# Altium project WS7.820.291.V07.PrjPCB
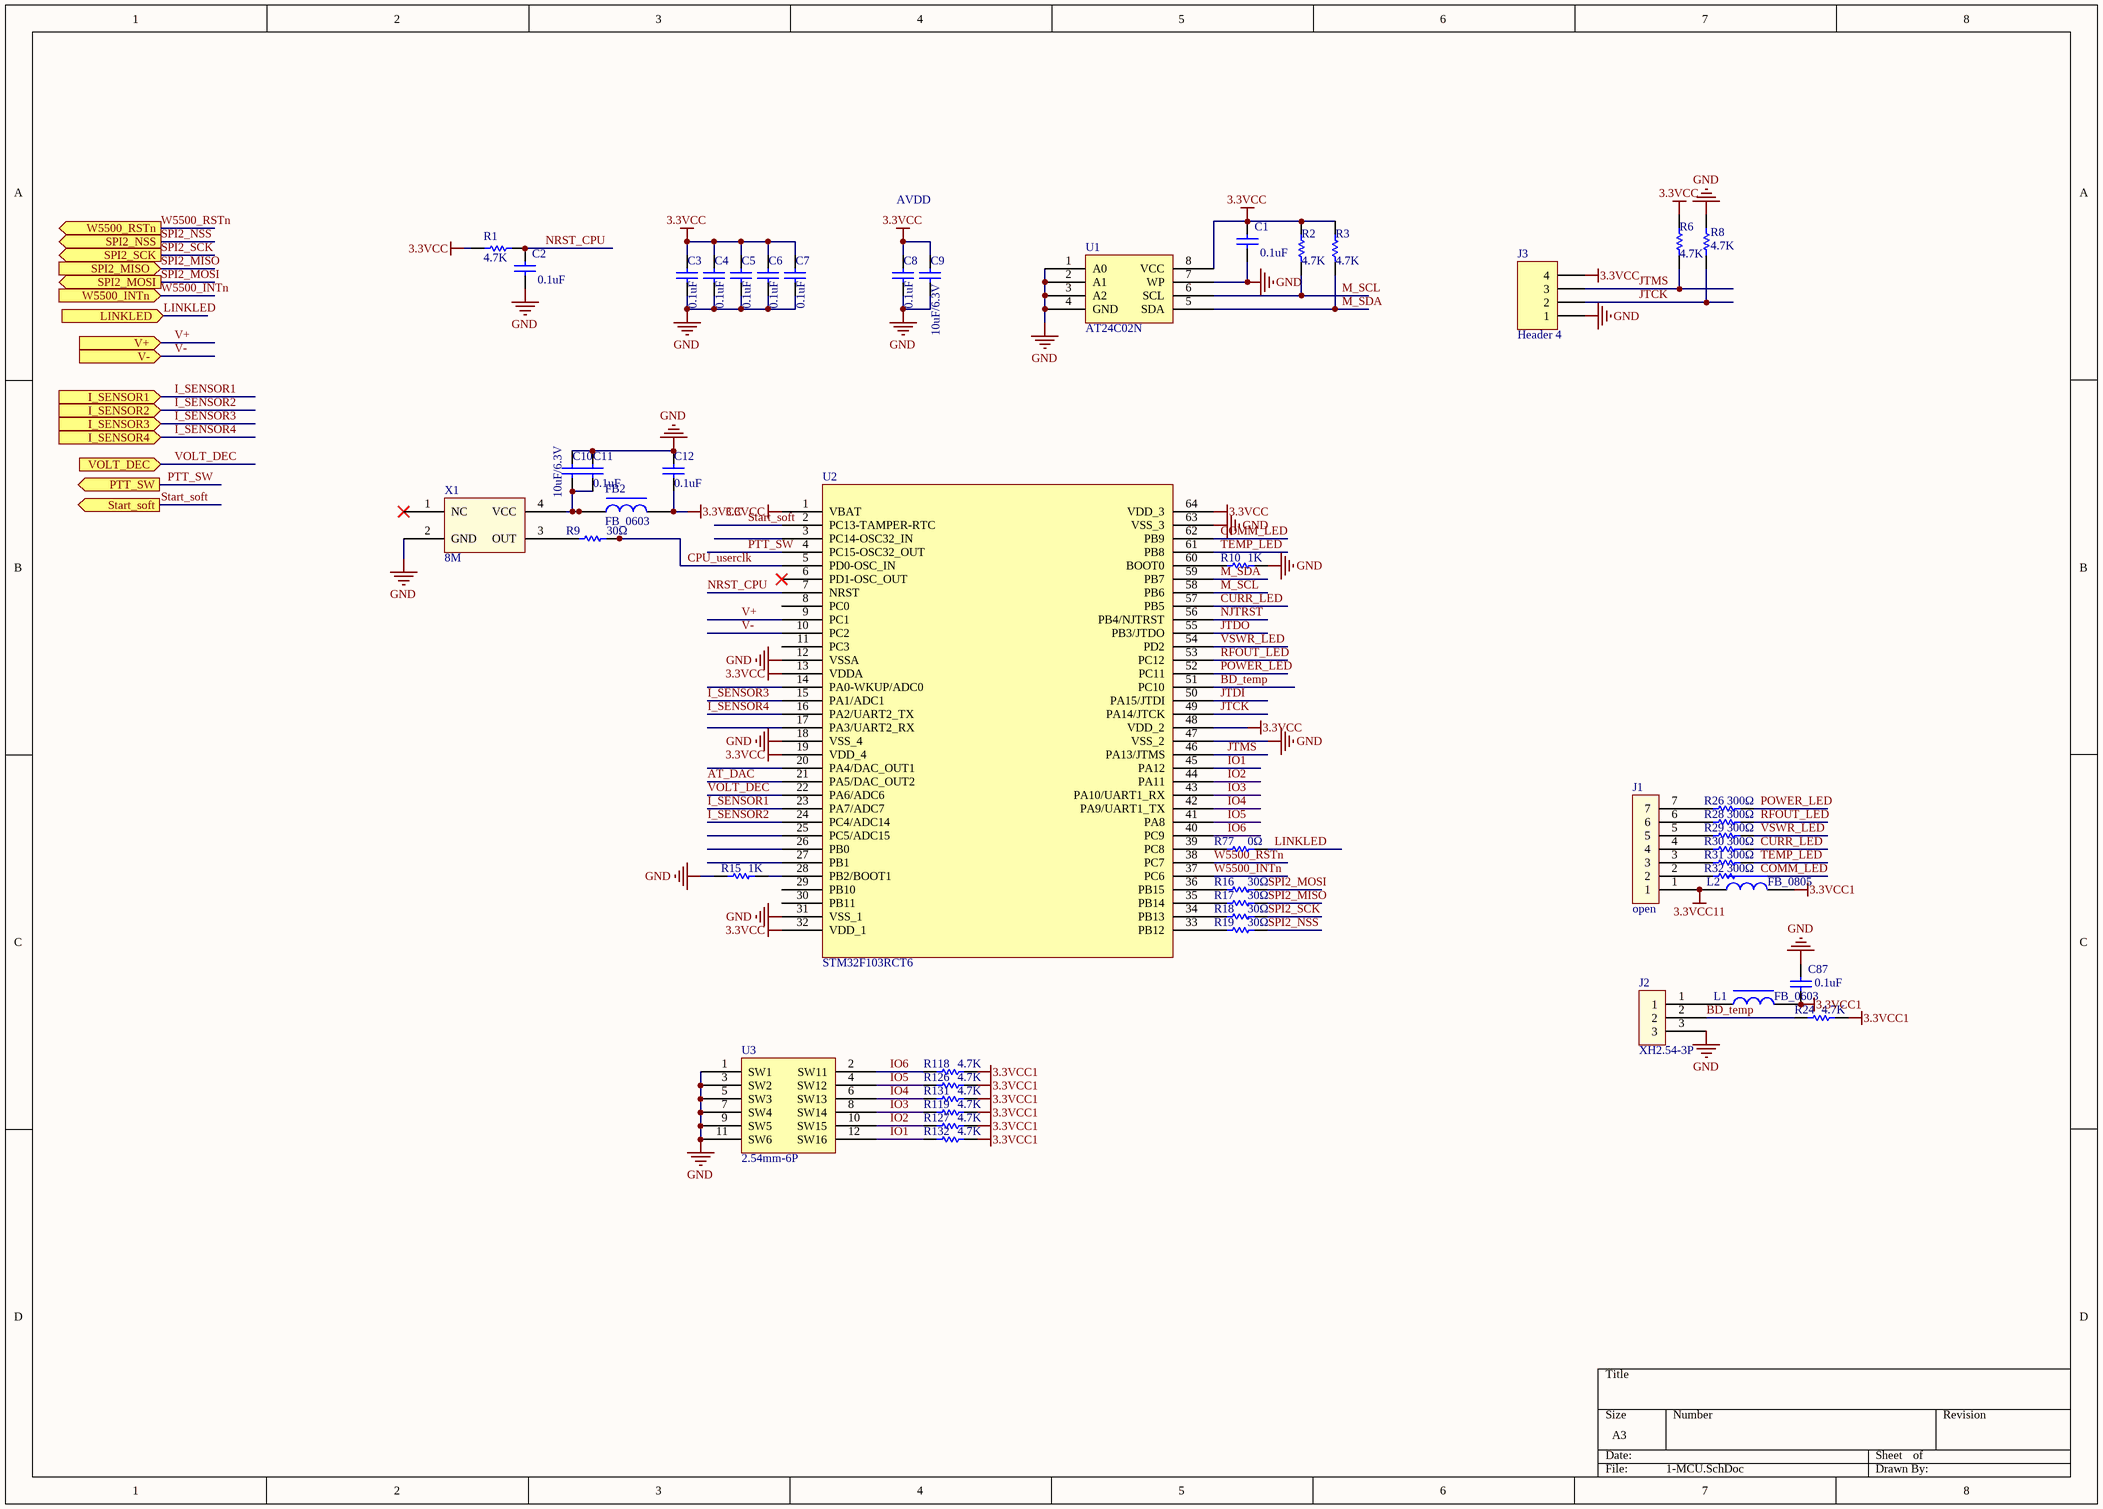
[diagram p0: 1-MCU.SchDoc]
4 sheets, 262 parts. Net scope: flat (ports and power ports of the same name join across sheets).
Board file: WS7.820.291.V07.PcbDoc
Sheets:
  1-MCU.SchDoc
  2-RJ45.SchDoc
  3-RF.SchDoc
  4-POWER.SchDoc

## Sheet 1-MCU.SchDoc
size A3

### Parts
C1  0.1uF  [C0603]
C2  0.1uF  [C0603]
C3  0.1uF  [C0603]
C4  0.1uF  [C0603]
C5  0.1uF  [C0603]
C6  0.1uF  [C0603]
C7  0.1uF  [C0603]
C8  0.1uF  [C0603]
C9  10uF/6.3V  [C0603]
C10  10uF/6.3V  [C0603]
C11  0.1uF  [C0603]
C12  0.1uF  [C0603]
C87  0.1uF  [C0603]
FB2  FB_0603  [L0603]
J1  open  [KF2510-7P -2R54-17R8x6R0-wanzhen]
J2  XH2.54-3P  [XH2.54mm-10R0x7R0--zhizhen]
J3  Header 4  [HDR1X4]
L1  FB_0603  [L0603]
L2  FB_0805  [L0805]
R1  4.7K  [R0603]
R2  4.7K  [R0603]
R3  4.7K  [R0603]
R6  4.7K  [R0603]
R8  4.7K  [R0603]
R9  30Ω  [R0603]
R10  1K  [R0603]
R15  1K  [R0603]
R16  30Ω  [R0603]
R17  30Ω  [R0603]
R18  30Ω  [R0603]
R19  30Ω  [R0603]
R24  4.7K  [R0603]
R26  300Ω  [R0603]
R28  300Ω  [R0603]
R29  300Ω  [R0603]
R30  300Ω  [R0603]
R31  300Ω  [R0603]
R32  300Ω  [R0603]
R77  0Ω  [R0603]
R118  4.7K  [R0603]
R119  4.7K  [R0603]
R126  4.7K  [R0603]
R127  4.7K  [R0603]
R131  4.7K  [R0603]
R132  4.7K  [R0603]
U1  AT24C02N  [SOIC8_1R27_3R9x4R9]
U2  STM32F103RCT6  [LQFP64-0R50-10x10]
U3  2.54mm-6P  [con12TM-2R54-2X6-boma]
X1  8M  [CRY4SM-5R0x7R0]

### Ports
I_SENSOR1 (in), I_SENSOR2 (in), I_SENSOR3 (in), I_SENSOR4 (in), LINKLED (in), PTT_SW (out), SPI2_MISO (in), SPI2_MOSI (out), SPI2_NSS (out), SPI2_SCK (out), Start_soft (out), V+ (in), V- (in), VOLT_DEC (in), W5500_INTn (in), W5500_RSTn (out)

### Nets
3.3VCC: C1.2 C3.2 C4.2 C5.2 C6.2 C7.2 C8.2 C9.2 C12.1 FB2.2 J3.4 R1.2 R2.2 R3.2 R6.2 U1.8(VCC) U2.1(VBAT) U2.13(VDDA) U2.19(VDD_4) U2.32(VDD_1) U2.48(VDD_2) U2.64(VDD_3)
3.3VCC1: C87.2 L1.2 L2.2 R24.1 R118.2 R119.2 R126.2 R127.2 R131.2 R132.2
3.3VCC11: J1.1 L2.1
GND: C1.1 C2.1 C3.1 C4.1 C5.1 C6.1 C7.1 C8.1 C9.1 C10.1 C11.2 C12.2 C87.1 J2.3 J3.1 R8.1 R10.1 R15.1 U1.1(A0) U1.2(A1) U1.3(A2) U1.4(GND) U1.7(WP) U2.12(VSSA) U2.18(VSS_4) U2.31(VSS_1) U2.47(VSS_2) U2.63(VSS_3) U3.1(SW1) U3.3(SW2) U3.5(SW3) U3.7(SW4) U3.9(SW5) U3.11(SW6) X1.2(GND)
AT_DAC: U2.21(PA5/DAC_OUT2)
BD_temp: J2.2 R24.2 U2.51(PC10)
COMM_LED: R32.2 U2.62(PB9)
CPU_userclk: R9.2 U2.5(PD0-OSC_IN)
CURR_LED: R30.2 U2.57(PB5)
I_SENSOR1: U2.23(PA7/ADC7) ; port I_SENSOR1
I_SENSOR2: U2.24(PC4/ADC14) ; port I_SENSOR2
I_SENSOR3: U2.15(PA1/ADC1) ; port I_SENSOR3
I_SENSOR4: U2.16(PA2/UART2_TX) ; port I_SENSOR4
IO1: R132.1 U2.45(PA12) U3.12(SW16)
IO2: R127.1 U2.44(PA11) U3.10(SW15)
IO3: R119.1 U2.43(PA10/UART1_RX) U3.8(SW14)
IO4: R131.1 U2.42(PA9/UART1_TX) U3.6(SW13)
IO5: R126.1 U2.41(PA8) U3.4(SW12)
IO6: R118.1 U2.40(PC9) U3.2(SW11)
JTCK: J3.2 R8.2 U2.49(PA14/JTCK)
JTDI: U2.50(PA15/JTDI)
JTDO: U2.55(PB3/JTDO)
JTMS: J3.3 R6.1 U2.46(PA13/JTMS)
LINKLED: R77.2 ; port LINKLED
M_SCL: R2.1 U1.6(SCL) U2.58(PB6)
M_SDA: R3.1 U1.5(SDA) U2.59(PB7)
NJTRST: U2.56(PB4/NJTRST)
NRST_CPU: C2.2 R1.1 U2.7(NRST)
POWER_LED: R26.2 U2.52(PC11)
PTT_SW: U2.4(PC15-OSC32_OUT) ; port PTT_SW
RFOUT_LED: R28.2 U2.53(PC12)
SPI2_MISO: R17.2 ; port SPI2_MISO
SPI2_MOSI: R16.2 ; port SPI2_MOSI
SPI2_NSS: R19.2 ; port SPI2_NSS
SPI2_SCK: R18.2 ; port SPI2_SCK
Start_soft: U2.2(PC13-TAMPER-RTC) ; port Start_soft
TEMP_LED: R31.2 U2.61(PB8)
V+: U2.9(PC1) ; port V+
V-: U2.10(PC2) ; port V-
VOLT_DEC: U2.22(PA6/ADC6) ; port VOLT_DEC
VSWR_LED: R29.2 U2.54(PD2)
W5500_INTn: U2.37(PC6) ; port W5500_INTn
W5500_RSTn: U2.38(PC7) ; port W5500_RSTn
NetC10_2: C10.2 C11.1 FB2.1 X1.4(VCC)
NetJ1_2: J1.2 R32.1
NetJ1_3: J1.3 R31.1
NetJ1_4: J1.4 R30.1
NetJ1_5: J1.5 R29.1
NetJ1_6: J1.6 R28.1
NetJ1_7: J1.7 R26.1
NetJ2_1: J2.1 L1.1
NetR9_1: R9.1 X1.3(OUT)
NetR10_2: R10.2 U2.60(BOOT0)
NetR15_2: R15.2 U2.28(PB2/BOOT1)
NetR16_1: R16.1 U2.36(PB15)
NetR17_1: R17.1 U2.35(PB14)
NetR18_1: R18.1 U2.34(PB13)
NetR19_1: R19.1 U2.33(PB12)
NetR77_1: R77.1 U2.39(PC8)

Not connected (* = marked no-connect by the designer): U2 3(PC14-OSC32_IN) 6(PD1-OSC_OUT)* 8(PC0) 11(PC3) 14(PA0-WKUP/ADC0) 17(PA3/UART2_RX) 20(PA4/DAC_OUT1) 25(PC5/ADC15) 26(PB0) 27(PB1) 29(PB10) 30(PB11); X1 1(NC)*

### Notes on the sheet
- AVDD

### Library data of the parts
C1-C8 C11 C12 = 0.1uF贴片电容: 贴片电容_GRM188R71H104KA01D_0.1uF±10%,50V,0603; code: 01010045
C9 C10 = 10uF贴片电容: 贴片电容_GRM188R60J106ME47D_10uF±20%,6.3V,0603; code: 01010037
C87 = 0.1uF: GRM188R71H104KA01D; MPN: MURATA; WSPN: 01010045; DESCRIPTION: CAP,0.1uF,±10%,50V,X7R,0603
FB2 = 0603贴片磁珠: 贴片磁珠_100R,0603; code: 0103016
J1 = KF2510-7P连接器: 连接器_KF2510-7P_直插,间距2.54mm; code: 01090014
J2 = XH2.54-3P: 连接器_XH2.54-3P_弯针,间距2.54mm
J3 = Header 4: Header, 4-Pin
L1 = 0805贴片磁珠: 贴片磁珠_600R,0805
L2 = 0805贴片磁珠: 贴片磁珠_600R,0805; code: 01030023
R1-R3 R6 R24 = 4.7K贴片电阻: 贴片电阻_4.7K±5%,0603; code: 01020012
R8 R10 R15 = 1K贴片电阻: 贴片电阻_1K±5%,0603; code: 01020082
R9 R16-R19 = 30Ω贴片电阻: 贴片电阻_30Ω±5%,0603; code: 01020108
R26 R28-R32 = 300Ω贴片电阻: 贴片电阻_300Ω±5%,0603; code: 01020008
R77 = 0Ω贴片电阻: 贴片电阻_0Ω±5%,0603; code: 01020010
R118 R119 R126 R127 R131 R132 = 1.5K贴片电阻: 贴片电阻_4.7K±5%,0603; code: 01020012
U1 = AT24C02N: EEPROM_AT24C02N_SOIC8; Maker: ATMEL; code: 01060068
U2 = STM32F103RCT6: MCU_STM32F103RCT6_32bit,LQFP64; code: 01060070; maker: ST
U3 = 拨码开关: 拨码开关_2.54mm-6P_侧拨
X1 = 16M贴片有源晶振: 贴片有源晶振_8M,20ppm,封装5x7

## Sheet 2-RJ45.SchDoc
size A3
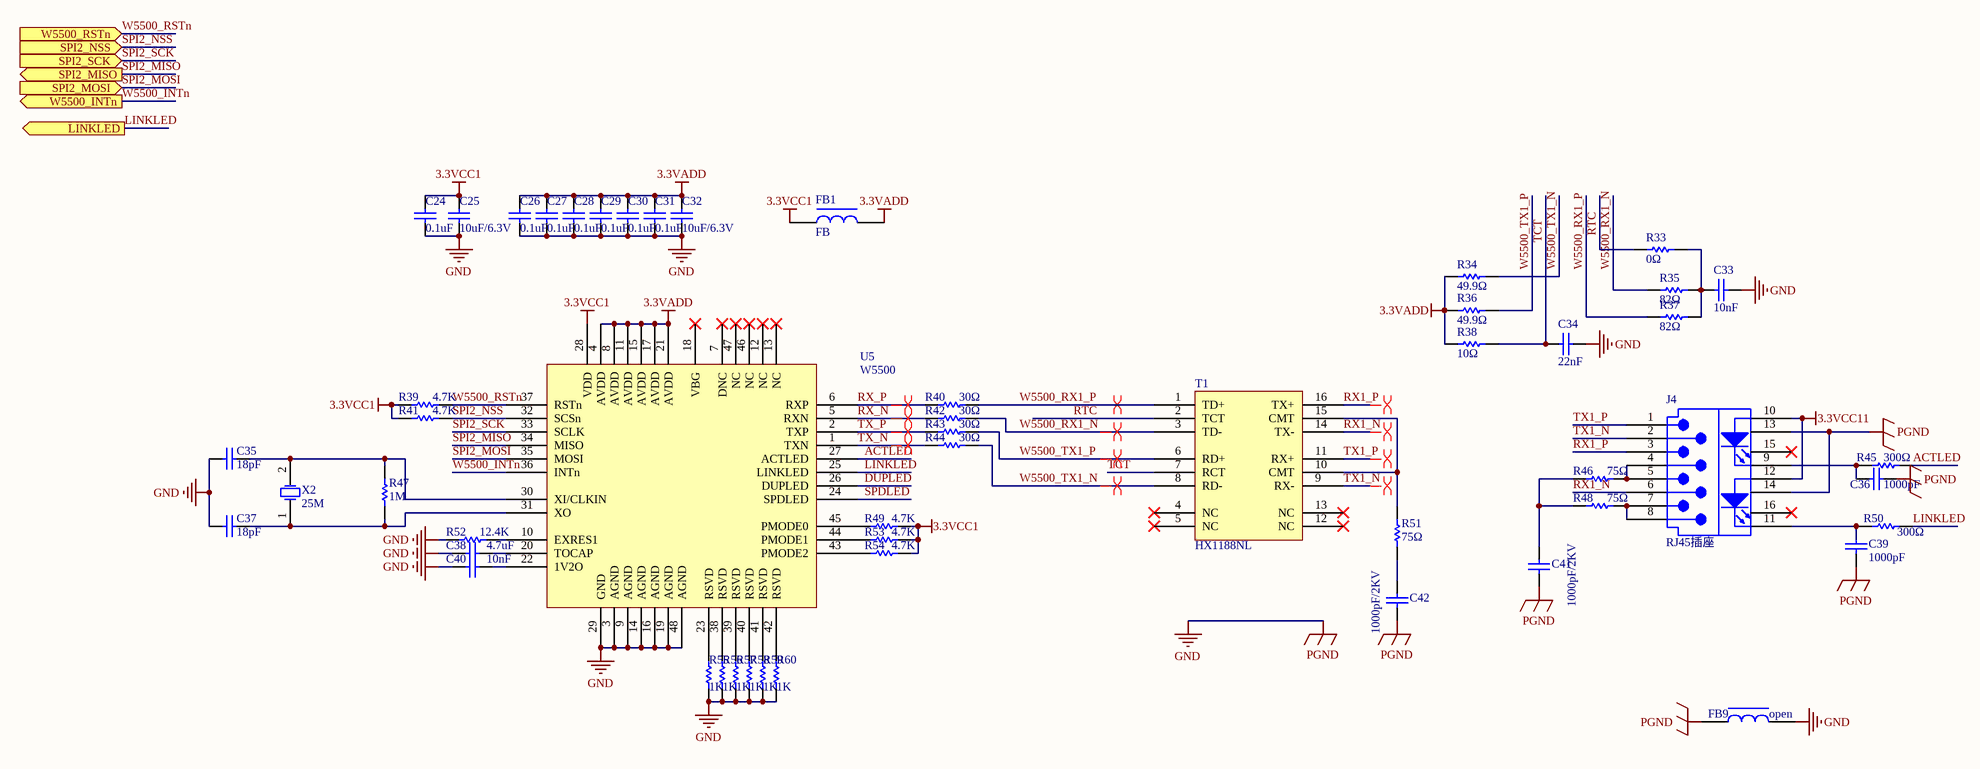
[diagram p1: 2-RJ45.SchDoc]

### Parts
C24  0.1uF  [C0603]
C25  10uF/6.3V  [C0603]
C26  0.1uF  [C0603]
C27  0.1uF  [C0603]
C28  0.1uF  [C0603]
C29  0.1uF  [C0603]
C30  0.1uF  [C0603]
C31  0.1uF  [C0603]
C32  10uF/6.3V  [C0603]
C33  10nF  [C0603]
C34  22nF  [C0603]
C35  18pF  [C0603]
C36  1000pF  [C0603]
C37  18pF  [C0603]
C38  4.7uF  [C0603]
C39  1000pF  [C0603]
C40  10nF  [C0603]
C41  1000pF/2KV  [C1206]
C42  1000pF/2KV  [C1206]
FB1  FB  [L0805]
FB9  open  [L0805]
J4  RJ45插座  [RJ45TH-1x1-2R54-LED]
R33  0Ω  [R0603]
R34  49.9Ω  [R0603]
R35  82Ω  [R0603]
R36  49.9Ω  [R0603]
R37  82Ω  [R0603]
R38  10Ω  [R0603]
R39  4.7K  [R0603]
R40  30Ω  [R0603]
R41  4.7K  [R0603]
R42  30Ω  [R0603]
R43  30Ω  [R0603]
R44  30Ω  [R0603]
R45  300Ω  [R0603]
R46  75Ω  [R0805]
R47  1M  [R0603]
R48  75Ω  [R0805]
R49  4.7K  [R0603]
R50  300Ω  [R0603]
R51  75Ω  [R1206]
R52  12.4K  [R0603]
R53  4.7K  [R0603]
R54  4.7K  [R0603]
R55  1K  [R0603]
R56  1K  [R0603]
R57  1K  [R0603]
R58  1K  [R0603]
R59  1K  [R0603]
R60  1K  [R0603]
T1  HX1188NL  [SOP16-1R27-7R11x12R7]
U5  W5500  [TQFN48-0R5-7X7]
X2  25M  [CRY2SM-6R0x3R5]

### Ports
LINKLED (out), SPI2_MISO (out), SPI2_MOSI (in), SPI2_NSS (in), SPI2_SCK (in), W5500_INTn (out), W5500_RSTn (in)

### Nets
3.3VADD: C26.2 C27.2 C28.2 C29.2 C30.2 C31.2 C32.2 FB1.2 R34.2 R36.2 R38.2 U5.4(AVDD) U5.8(AVDD) U5.11(AVDD) U5.15(AVDD) U5.17(AVDD) U5.21(AVDD)
3.3VCC1: C24.2 C25.2 FB1.1 R39.2 R41.2 R49.2 R53.2 R54.2 U5.28(VDD)
3.3VCC11: J4.10(A1) J4.12(A2)
GND: C24.1 C25.1 C26.1 C27.1 C28.1 C29.1 C30.1 C31.1 C32.1 C33.1 C34.1 C35.1 C36.1 C37.1 C38.1 C39.1 C40.1 C41.1 C42.1 FB9.1 FB9.2 J4.13 J4.14 R52.1 R55.1 R56.1 R57.1 R58.1 R59.1 R60.1 U5.3(AGND) U5.9(AGND) U5.14(AGND) U5.16(AGND) U5.19(AGND) U5.29(GND) U5.48(AGND)  [also labelled PGND]
ACTLED: R45.2 U5.27(ACTLED)
DUPLED: U5.26(DUPLED)
LINKLED: R50.2 U5.25(LINKLED) ; port LINKLED
RTC: R33.2 T1.2(TCT)
RX1_N: J4.6(RX-) T1.14(TX-)
RX1_P: J4.3(RX+) T1.16(TX+)
RX_N: R42.1 U5.5(RXN)
RX_P: R40.1 U5.6(RXP)
SPDLED: U5.24(SPDLED)
SPI2_MISO: U5.34(MISO) ; port SPI2_MISO
SPI2_MOSI: U5.35(MOSI) ; port SPI2_MOSI
SPI2_NSS: R41.1 U5.32(SCSn) ; port SPI2_NSS
SPI2_SCK: U5.33(SCLK) ; port SPI2_SCK
TCT: C34.2 R38.1 T1.7(RCT)
TX1_N: J4.2(TX-) T1.9(RX-)
TX1_P: J4.1(TX+) T1.11(RX+)
TX_N: R44.1 U5.1(TXN)
TX_P: R43.1 U5.2(TXP)
W5500_INTn: U5.36(INTn) ; port W5500_INTn
W5500_RSTn: R39.1 U5.37(RSTn) ; port W5500_RSTn
W5500_RX1_N: R35.2 R42.2 T1.3(TD-)
W5500_RX1_P: R37.2 R40.2 T1.1(TD+)
W5500_TX1_N: R34.1 R44.2 T1.8(RD-)
W5500_TX1_P: R36.1 R43.2 T1.6(RD+)
NetC33_2: C33.2 R33.1 R35.1 R37.1
NetC35_2: C35.2 R47.2 U5.30(XI/CLKIN) X2.2(OSC2)
NetC36_2: C36.2 J4.9(K1) R45.1
NetC37_2: C37.2 R47.1 U5.31(XO) X2.1(OSC1)
NetC38_2: C38.2 U5.20(TOCAP)
NetC39_2: C39.2 J4.11(K2) R50.1
NetC40_2: C40.2 U5.22(1V2O)
NetC41_2: C41.2 R46.1 R48.1
NetC42_2: C42.2 R51.1
NetJ4_4: J4.4(NC) J4.5(NC) R46.2
NetJ4_7: J4.7(NC) J4.8(NC) R48.2
NetR49_1: R49.1 U5.45(PMODE0)
NetR51_2: R51.2 T1.10(CMT) T1.15(CMT)
NetR52_2: R52.2 U5.10(EXRES1)
NetR53_1: R53.1 U5.44(PMODE1)
NetR54_1: R54.1 U5.43(PMODE2)
NetR55_2: R55.2 U5.23(RSVD)
NetR56_2: R56.2 U5.38(RSVD)
NetR57_2: R57.2 U5.39(RSVD)
NetR58_2: R58.2 U5.40(RSVD)
NetR59_2: R59.2 U5.41(RSVD)
NetR60_2: R60.2 U5.42(RSVD)

Not connected (* = marked no-connect by the designer): J4 15* 16*; T1 4(NC)* 5(NC)* 12(NC)* 13(NC)*; U5 7(DNC)* 12(NC)* 13(NC)* 18(VBG)* 46(NC)* 47(NC)*

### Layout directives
differential pair: RX1_N, RX1_P, RX_N, RX_P, TX1_N, TX1_P, TX_N, TX_P, W5500_RX1_N, W5500_RX1_P, W5500_TX1_N, W5500_TX1_P

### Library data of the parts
C24 C26-C31 = 0.1uF贴片电容: as C1 on sheet 1-MCU
C25 C32 = 10uF贴片电容: as C9 on sheet 1-MCU
C33 C40 = 0.1uF贴片电容: 贴片电容_10nF±10%,50V,0603
C34 = 27nF贴片电容: 贴片电容_22nF±5%,50V,0603; code: 01010054
C35 C37 = 20pF贴片电容: 贴片电容_18pF±5%,50V,0603
C36 C39 = 1000pF贴片电容: 贴片电容_GRM188R71H102KA01_1000pF±10%,50V,0603; code: 01010093
C38 = 1uF贴片电容: 贴片电容_4.7uF±10%,50V,0603
C41 C42 = 10uF贴片电容: 贴片电容_1000pF/2KV
FB1 FB9 = 0805贴片磁珠: 贴片磁珠_600R,0805; code: 01030023
J4 = RJ45弯脚带灯: RJ45插座_1*1,带左黄右绿灯,弯脚; MPN: 朱迅; code: 01090042
R33 = 0Ω贴片电阻: 贴片电阻_0Ω±5%,0603; code: 01020010
R34 R36 = 51Ω贴片电阻: 贴片电阻_49.9Ω±1%,0603; code: 01020126
R35 R37 = 51Ω贴片电阻: 贴片电阻_82Ω±1%,0603; code: 01020196
R38 = 10Ω贴片电阻: 贴片电阻_10Ω±5%,0603; code: 01020104
R39 R41 R49 R53 R54 = 4.7K贴片电阻: 贴片电阻_4.7K±5%,0603; code: 01020012
R40 R42-R44 = 30Ω贴片电阻: 贴片电阻_30Ω±5%,0603; code: 01020108
R45 R50 = 300Ω贴片电阻: 贴片电阻_300Ω±5%,0603; code: 01020008
R46 R48 = 75Ω贴片电阻: 贴片电阻_75Ω±5%,0805; code: 01020068
R47 = 1M贴片电阻: 贴片电阻_1M±5%,0603; code: 01020093
R51 = 75Ω贴片电阻: 贴片电阻_75Ω±5%,1206; code: 01020197
R52 = 12K贴片电阻: 贴片电阻_12.4K±1%,0603
R55-R60 = 1K贴片电阻: 贴片电阻_1K±5%,0603; code: 01020082
T1 = HX1188NL: 网络变压器_HX1188NL_百兆,SOIC16; code: 01060114
U5 = W5500: 以太网控制器_W5500_LQFP48; code: 01060113
X2 = 25M贴片无源晶体: 贴片无源晶体_25MHz,30ppm,6035封装; code: 03050012

## Sheet 3-RF.SchDoc
size A3
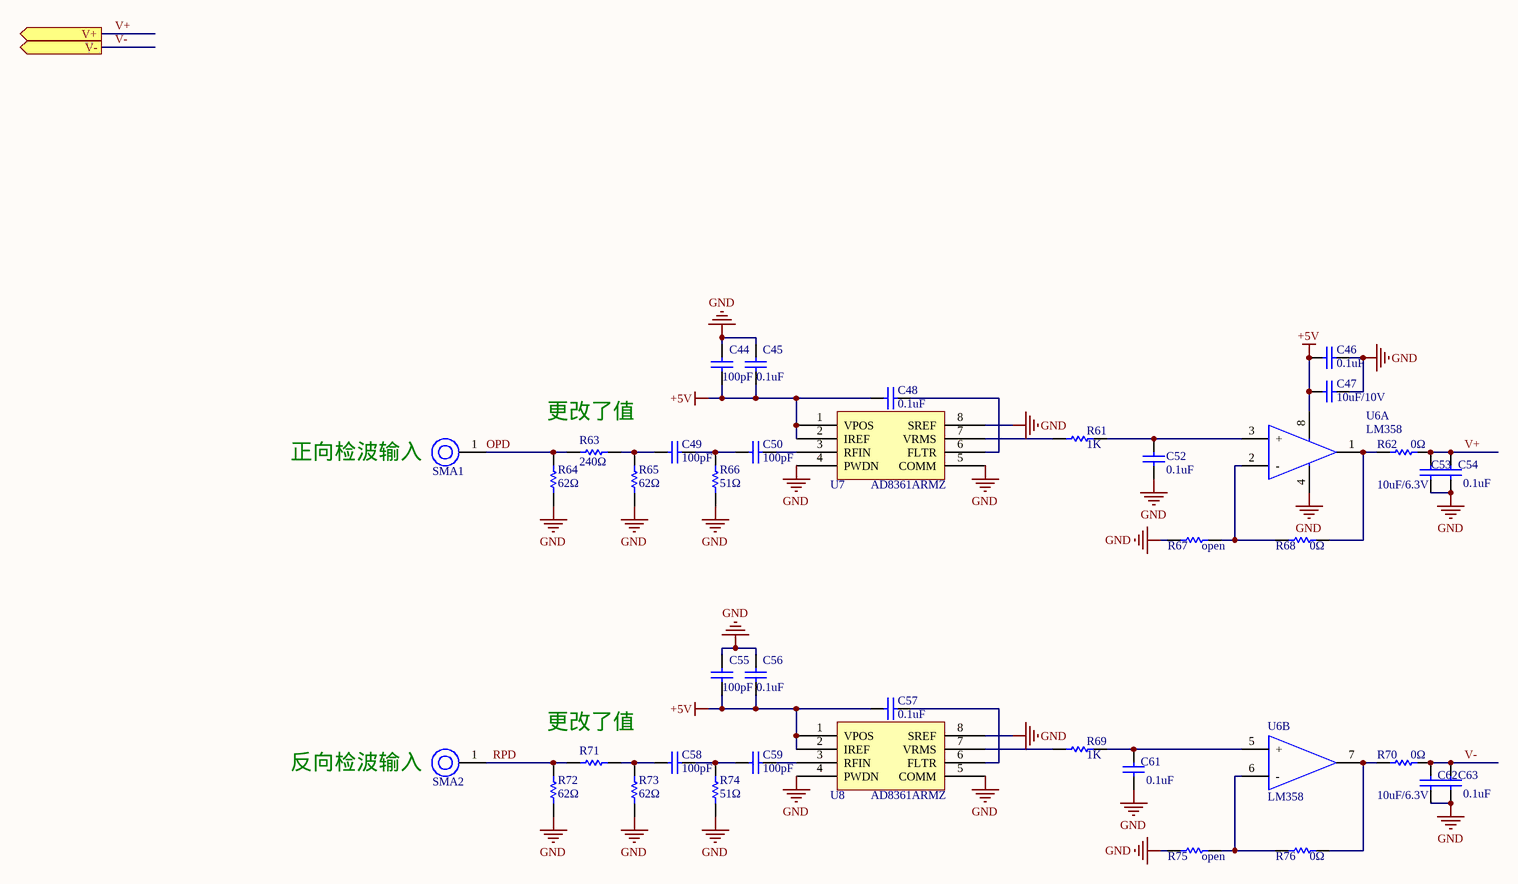
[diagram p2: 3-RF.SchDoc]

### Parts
C44  100pF  [C0603]
C45  0.1uF  [C0603]
C46  0.1uF  [C0603]
C47  10uF/10V  [C0805]
C48  0.1uF  [C0603]
C49  100pF  [C0805]
C50  100pF  [C0805]
C52  0.1uF  [C0603]
C53  10uF/6.3V  [C0603]
C54  0.1uF  [C0603]
C55  100pF  [C0603]
C56  0.1uF  [C0603]
C57  0.1uF  [C0603]
C58  100pF  [C0805]
C59  100pF  [C0805]
C61  0.1uF  [C0603]
C62  10uF/6.3V  [C0603]
C63  0.1uF  [C0603]
R61  1K  [R0603]
R62  0Ω  [R0603]
R63  240Ω  [R1206]
R64  62Ω  [R1206]
R65  62Ω  [R1206]
R66  51Ω  [R0805]
R67  open  [R0603]
R68  0Ω  [R0603]
R69  1K  [R0603]
R70  0Ω  [R0603]
R71  (no value)  [R1206]
R72  62Ω  [R1206]
R73  62Ω  [R1206]
R74  51Ω  [R0805]
R75  open  [R0603]
R76  0Ω  [R0603]
SMA1  SMA-50KFD-4  [SMA-50KFD-4]  (value not drawn)
SMA2  SMA-50KFD-4  [SMA-50KFD-4]  (value not drawn)
U6  LM358  [SOIC8_1R27_3R9x4R9]  (parts A,B of 2)
U7  AD8361ARMZ  [micro_SOIC8-0R65-3x3]
U8  AD8361ARMZ  [micro_SOIC8-0R65-3x3]

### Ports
V+ (out), V- (out)

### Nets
+5V: C44.1 C45.1 C46.1 C47.1 C48.2 C55.1 C56.1 C57.2 U6.8 U7.1(VPOS) U7.2(IREF) U8.1(VPOS) U8.2(IREF)
GND: C44.2 C45.2 C46.2 C47.2 C52.1 C53.1 C54.1 C55.2 C56.2 C61.1 C62.1 C63.1 R64.1 R65.1 R66.1 R67.1 R72.1 R73.1 R74.1 R75.1 U6.4 U7.4(PWDN) U7.5(COMM) U7.8(SREF) U8.4(PWDN) U8.5(COMM) U8.8(SREF)
OPD: R63.1 R64.2 SMA1.1(Sig)
RPD: R71.1 R72.2 SMA2.1(Sig)
V+: C53.2 C54.2 R62.2 ; port V+
V-: C62.2 C63.2 R70.2 ; port V-
NetC48_1: C48.1 U7.6(FLTR)
NetC49_1: C49.1 R63.2 R65.2
NetC49_2: C49.2 C50.1 R66.2
NetC50_2: C50.2 U7.3(RFIN)
NetC52_2: C52.2 R61.2 U6.3(+)
NetC57_1: C57.1 U8.6(FLTR)
NetC58_1: C58.1 R71.2 R73.2
NetC58_2: C58.2 C59.1 R74.2
NetC59_2: C59.2 U8.3(RFIN)
NetC61_2: C61.2 R69.2 U6.5(+)
NetR61_1: R61.1 U7.7(VRMS)
NetR62_1: R62.1 R68.2 U6.1
NetR67_2: R67.2 R68.1 U6.2(-)
NetR69_1: R69.1 U8.7(VRMS)
NetR70_1: R70.1 R76.2 U6.7
NetR75_2: R75.2 R76.1 U6.6(-)

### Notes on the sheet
- 更改了值
- 正向检波输入
- 反向检波输入

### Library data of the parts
C44 C55 = 220pF贴片电容: 贴片电容_100pF±10%,50V,0603
C45 C46 C48 C52 C54 C56 C57 C61 C63 = 0.1uF贴片电容: as C1 on sheet 1-MCU
C47 = 10uF贴片电容: 贴片电容_GRM21BR61A106KE19L_10uF±10%,10V,0805; code: 01010036
C49 C50 C58 C59 = 100pF贴片电容: 贴片电容_GRM2165C1H101JA01D_100pF±5%,50V,0805; code: 01010043
C53 C62 = 10uF贴片电容: as C9 on sheet 1-MCU
R61 R69 = 1K贴片电阻: 贴片电阻_1K±5%,0603; code: 01020082
R62 R68 R70 R76 = 0Ω贴片电阻: 贴片电阻_0Ω±5%,0603; code: 01020010
R63 = 300Ω贴片电阻: code: 01020037
R64 R65 R72 R73 = 62Ω贴片电阻: code: 01020035
R66 R74 = 51Ω贴片电阻: 贴片电阻_51Ω±5%,0805; code: 01020023
R67 R75 = 0Ω贴片电阻
R71 = 300Ω贴片电阻: 贴片电阻_300Ω±5%,0805; code: 01020037
SMA1 SMA2 = SMA-50KFD-4: 射频同轴连接器_SMA-50KFD-4; code: 03100009
U6 = LM358: 运算放大器_LM358_SOIC8; Maker: MOTOROLA; code: 01060025
U7 U8 = AD8361ARMZ: 检波器_AD8361ARMZ_LF to 2.5 GHz,SOIC8; Maker: ADI; code: 01060004

## Sheet 4-POWER.SchDoc
size A3
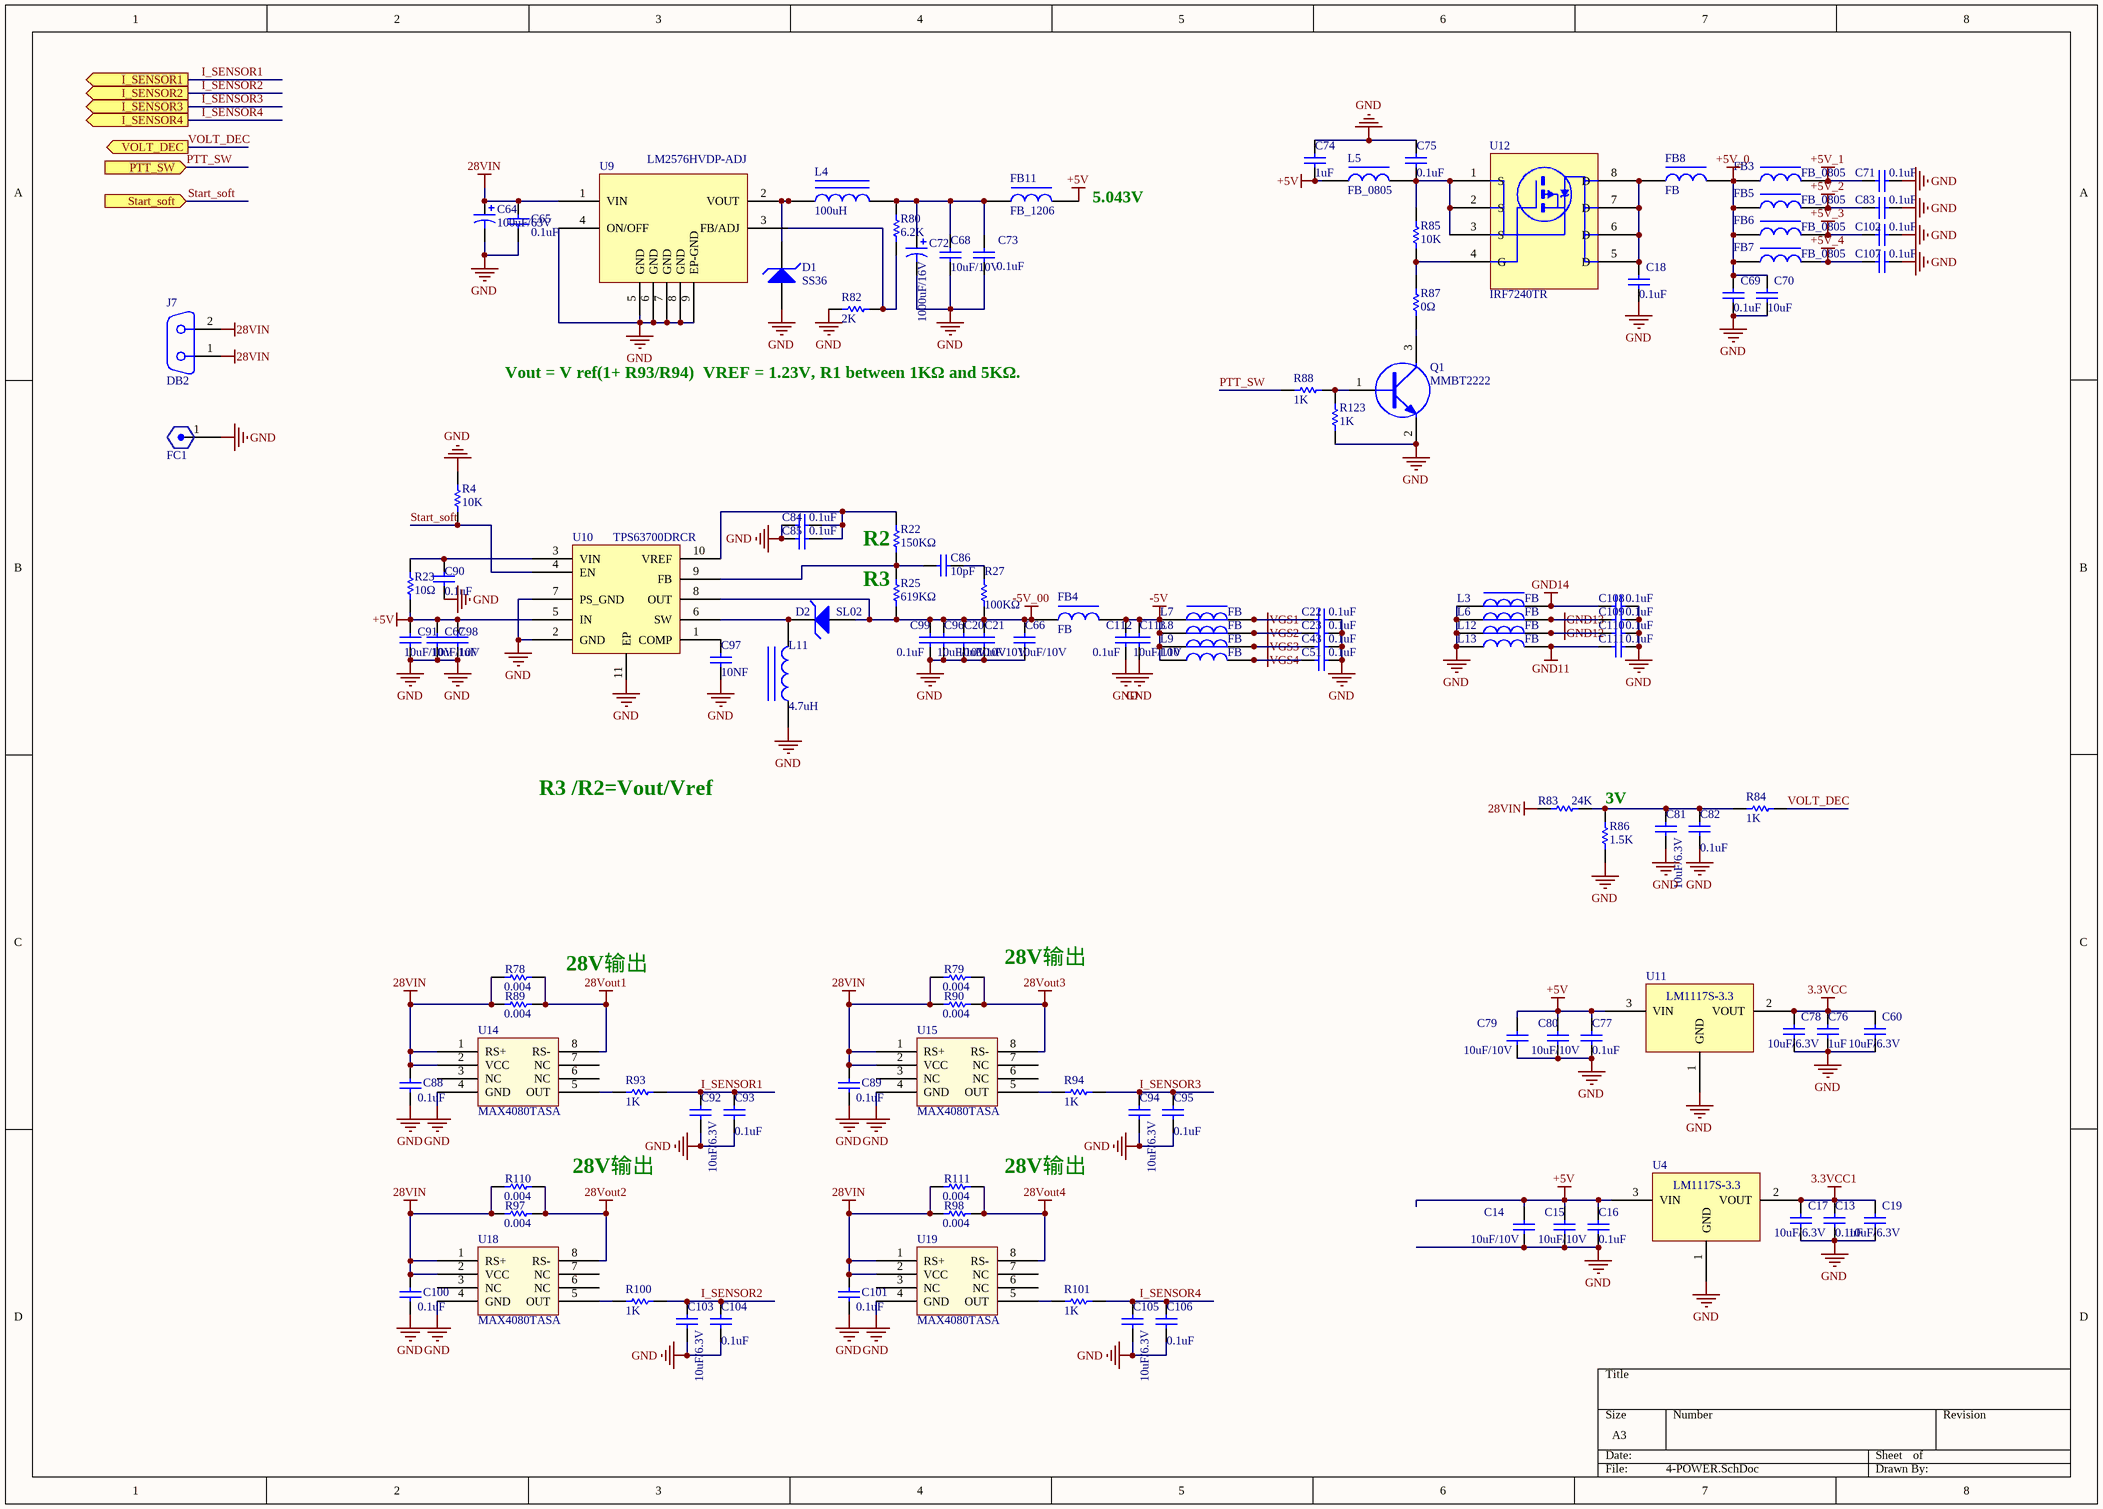
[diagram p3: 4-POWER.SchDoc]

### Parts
C13  0.1uF  [C0603]
C14  10uF/10V  [C0805]
C15  10uF/10V  [C0805]
C16  0.1uF  [C0603]
C17  10uF/6.3V  [C0603]
C18  0.1uF  [C0603]
C19  10uF/6.3V  [C0603]
C20  10uF/10V  [C0805]
C21  10uF/10V  [C0805]
C22  0.1uF  [C0603]
C23  0.1uF  [C0603]
C43  0.1uF  [C0603]
C51  0.1uF  [C0603]
C60  10uF/6.3V  [C0603]
C64  100uF/63V  [ECAP2SM_10R4x10R4]
C65  0.1uF  [C0603]
C66  10uF/10V  [C0805]
C67  10uF/10V  [C0805]
C68  10uF/10V  [C0805]
C69  0.1uF  [C0603]
C70  10uF  [C0603]
C71  0.1uF  [C0603]
C72  1000uF/16V  [ECAP2SM_10R4x10R4]
C73  0.1uF  [C0603]
C74  1uF  [C0603]
C75  0.1uF  [C0603]
C76  1uF  [C0603]
C77  0.1uF  [C0603]
C78  10uF/6.3V  [C0603]
C79  10uF/10V  [C0805]
C80  10uF/10V  [C0805]
C81  10uF/6.3V  [C0603]
C82  0.1uF  [C0603]
C83  0.1uF  [C0603]
C84  0.1uF  [C0603]
C85  0.1uF  [C0603]
C86  10pF  [C0603]
C88  0.1uF  [C0603]
C89  0.1uF  [C0603]
C90  0.1uF  [C0603]
C91  10uF/10V  [C0805]
C92  10uF/6.3V  [C0603]
C93  0.1uF  [C0603]
C94  10uF/6.3V  [C0603]
C95  0.1uF  [C0603]
C96  10uF/10V  [C0805]
C97  10NF  [C0603]
C98  1uF  [C0603]
C99  0.1uF  [C0603]
C100  0.1uF  [C0603]
C101  0.1uF  [C0603]
C102  0.1uF  [C0603]
C103  10uF/6.3V  [C0603]
C104  0.1uF  [C0603]
C105  10uF/6.3V  [C0603]
C106  0.1uF  [C0603]
C107  0.1uF  [C0603]
C108  0.1uF  [C0603]
C109  0.1uF  [C0603]
C110  0.1uF  [C0603]
C111  0.1uF  [C0603]
C112  0.1uF  [C0603]
C113  10uF/10V  [C0805]
D1  SS36  [DO-214AC]
D2  SL02  [SL02]
FB3  FB_0805  [L0805]
FB4  FB  [L0805]
FB5  FB_0805  [L0805]
FB6  FB_0805  [L0805]
FB7  FB_0805  [L0805]
FB8  FB  [L0805]
FB11  FB_1206  [L1206]
FC1  CT52-2-63V-2200PF  [FC-M4]  (value not drawn)
J7  DB2  [DB2TM-VM]
L3  FB  [L0805]
L4  100uH  [PL2SM-12R5x12R5]
L5  FB_0805  [L0805]
L6  FB  [L0805]
L7  FB  [L0805]
L8  FB  [L0805]
L9  FB  [L0805]
L10  FB  [L0805]
L11  4.7uH  [PL2SM-3R0x3R0]
L12  FB  [L0805]
L13  FB  [L0805]
Q1  MMBT2222  [SOT23-3]
R4  10K  [R0603]
R22  150KΩ  [R0603]
R23  10Ω  [R0603]
R25  619KΩ  [R0603]
R27  100KΩ  [R0603]
R78  0.004  [R2512]
R79  0.004  [R2512]
R80  6.2K  [R0603]
R82  2K  [R0603]
R83  24K  [R0603]
R84  1K  [C0603]
R85  10K  [R0603]
R86  1.5K  [R0603]
R87  0Ω  [R0603]
R88  1K  [R0603]
R89  0.004  [R2512]
R90  0.004  [R2512]
R93  1K  [R0603]
R94  1K  [R0603]
R97  0.004  [R2512]
R98  0.004  [R2512]
R100  1K  [R0603]
R101  1K  [R0603]
R110  0.004  [R2512]
R111  0.004  [R2512]
R123  1K  [R0603]
U4  LM1117S-3.3  [SOT-223]
U9  LM2576HVDP-ADJ  [SOIC8_1R27_3R9x4R9-1]
U10  TPS63700DRCR  [VSON10-0R5-3x3]
U11  LM1117S-3.3  [SOT-223]
U12  IRF7240TR  [SOIC8_1R27_3R9x4R9]
U14  MAX4080TASA  [SOIC8_1R27_3R9x4R9]
U15  MAX4080TASA  [SOIC8_1R27_3R9x4R9]
U18  MAX4080TASA  [SOIC8_1R27_3R9x4R9]
U19  MAX4080TASA  [SOIC8_1R27_3R9x4R9]

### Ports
I_SENSOR1 (out), I_SENSOR2 (out), I_SENSOR3 (out), I_SENSOR4 (out), PTT_SW (in), Start_soft (in), VOLT_DEC (out)

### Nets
3.3VCC: C60.2 C76.2 C78.2 U11.2(VOUT)
3.3VCC1: C13.2 C17.2 C19.2 U4.2(VOUT)
28VIN: C64.1 C65.2 C88.2 C89.2 C100.2 C101.2 J7.1 J7.2 R78.1 R79.1 R83.1 R89.1 R90.1 R97.1 R98.1 R110.1 R111.1 U9.1(VIN) U14.1(RS+) U14.2(VCC) U15.1(RS+) U15.2(VCC) U18.1(RS+) U18.2(VCC) U19.1(RS+) U19.2(VCC)
28Vout1: R78.2 R89.2 U14.8(RS-)
28Vout2: R97.2 R110.2 U18.8(RS-)
28Vout3: R79.2 R90.2 U15.8(RS-)
28Vout4: R98.2 R111.2 U19.8(RS-)
+5V: C14.2 C15.2 C16.2 C67.2 C74.1 C77.2 C79.2 C80.2 C91.2 C98.2 FB11.2 L5.1 R23.1 U4.3(VIN) U10.5(IN) U11.3(VIN)
+5V_0: C69.2 C70.2 FB3.1 FB5.1 FB6.1 FB7.1 FB8.2
+5V_1: C71.2 FB3.2
+5V_2: C83.2 FB5.2
+5V_3: C102.2 FB6.2
+5V_4: C107.2 FB7.2
-5V: C112.2 C113.2 FB4.2 L7.1 L8.1 L9.1 L10.1
-5V_00: C20.2 C21.2 C66.2 C96.2 C99.2 D2.1(A) FB4.1 R25.1 R27.1 U10.8(OUT)
GND: C13.1 C14.1 C15.1 C16.1 C17.1 C18.1 C19.1 C20.1 C21.1 C22.2 C23.2 C43.2 C51.2 C60.1 C64.2 C65.1 C66.1 C67.1 C68.1 C69.1 C70.1 C71.1 C72.2 C73.1 C74.2 C75.2 C76.1 C77.1 C78.1 C79.1 C80.1 C81.1 C82.1 C83.1 C84.2 C85.2 C88.1 C89.1 C90.1 C91.1 C92.1 C93.1 C94.1 C95.1 C96.1 C97.1 C98.1 C99.1 C100.1 C101.1 C102.1 C103.1 C104.1 C105.1 C106.1 C107.1 C108.2 C109.2 C110.2 C111.2 C112.1 C113.1 D1.1(A) FC1.1 L3.1 L6.1 L11.1 L12.1 L13.1 Q1.2(E) R4.2 R82.2 R86.1 R123.1 U4.1(GND) U9.4(ON/OFF) U9.5(GND) U9.6(GND) U9.7(GND) U9.8(GND) U9.9(EP-GND) U10.2(GND) U10.7(PS_GND) U10.11(EP) U11.1(GND) U14.4(GND) U15.4(GND) U18.4(GND) U19.4(GND)
GND11: C111.1 L13.2
GND12: C110.1 L12.2
GND13: C109.1 L6.2
GND14: C108.1 L3.2
VGS1: C22.1 L7.2
VGS2: C23.1 L8.2
VGS3: C43.1 L9.2
VGS4: C51.1 L10.2
I_SENSOR1: C92.2 C93.2 R93.2 ; port I_SENSOR1
I_SENSOR2: C103.2 C104.2 R100.2 ; port I_SENSOR2
I_SENSOR3: C94.2 C95.2 R94.2 ; port I_SENSOR3
I_SENSOR4: C105.2 C106.2 R101.2 ; port I_SENSOR4
PTT_SW: R88.1 ; port PTT_SW
Start_soft: R4.1 U10.4(EN) ; port Start_soft
VOLT_DEC: R84.1 ; port VOLT_DEC
NetC18_2: C18.2 FB8.1 U12.5(D) U12.6(D) U12.7(D) U12.8(D)
NetC68_2: C68.2 C72.1 C73.2 FB11.1 L4.2 R80.2
NetC75_1: C75.1 L5.2 R85.2 U12.1(S) U12.2(S) U12.3(S)
NetC81_2: C81.2 C82.2 R83.2 R84.2 R86.2
NetC84_1: C84.1 C85.1 R22.2 U10.10(VREF)
NetC86_1: C86.1 R22.1 R25.2 U10.9(FB)
NetC86_2: C86.2 R27.2
NetC90_2: C90.2 R23.2 U10.3(VIN)
NetC97_2: C97.2 U10.1(COMP)
NetD1_2: D1.2(K) L4.1 U9.2(VOUT)
NetD2_2: D2.2(K) L11.2 U10.6(SW)
NetQ1_1: Q1.1(B) R88.2 R123.2
NetQ1_3: Q1.3(C) R87.1
NetR80_1: R80.1 R82.1 U9.3(FB/ADJ)
NetR85_1: R85.1 R87.2 U12.4(G)
NetR93_1: R93.1 U14.5(OUT)
NetR94_1: R94.1 U15.5(OUT)
NetR100_1: R100.1 U18.5(OUT)
NetR101_1: R101.1 U19.5(OUT)

Not connected (* = marked no-connect by the designer): U14 3(NC) 6(NC) 7(NC); U15 3(NC) 6(NC) 7(NC); U18 3(NC) 6(NC) 7(NC); U19 3(NC) 6(NC) 7(NC)

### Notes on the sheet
- (near FB11) 5.043V
- Vout = V ref(1+ R93/R94)  VREF = 1.23V, R1 between 1KΩ and 5KΩ.
- R3
- (near R22) R2
- R3 /R2=Vout/Vref
- (near R86) 3V
- 28V输出

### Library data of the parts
C13 C74 C76 = 1uF贴片电容: 贴片电容_GRM188R61A105KA61D_1uF±10%,10V,0603; code: 01010038
C14 C15 C20 C21 C66-C68 C79 C80 C91 C96 C113 = 10uF贴片电容: as C47 on sheet 3-RF
C16 C65 C73 C75 C77 C82 C88 C89 C93 C95 C100 C101 C104 C106 = 0.1uF贴片电容: as C1 on sheet 1-MCU
C17 C19 C60 C78 C81 C92 C94 C103 C105 = 10uF贴片电容: as C9 on sheet 1-MCU
C18 C22 C23 C43 C51 C69 C71 C83-C85 C90 C99 C102 C107-C112 = 0.1uF: as C87 on sheet 1-MCU
C64 = 100uF/63V: 贴片电解电容_VEJ101M1JTR-1010_100uF/63V,±20%,表贴D10*H10; code: 01080002
C70 = 0.1uF: MPN: MURATA; WSPN: 01010045; DESCRIPTION: CAP,0.1uF,±10%,50V,X7R,0603
C72 = 1000uF/16V: 贴片电解电容_VE102M1CTR-1010_1000uF/16V,±20%,表贴10*10; code: 01080003
C86 = 10pF贴片电容: 贴片电容_0603CG100J500NT_10pF±5%,50V,0603; code: 01010001
C97 = 0.1uF: 0603,10NF,50V,±10％,X7R
C98 = 0.1uF
D1 = 肖特基整流二极管_SS36: 肖特基整流二极管_SS36_封装SMA,3A/60V; code: 01040003
D2 = 肖特基整流二极管_SS36: 肖特基整流二极管_SL02_1.1A/20V
FB3-FB8 L3 L5-L10 L12 L13 = 0805贴片磁珠: 贴片磁珠_600R,0805; code: 01030023
FB11 = 1206贴片磁珠: 贴片磁珠_30R,6A,1206; code: 0103015
FC1 = M4穿心电容: 穿心电容_CT52-2-63V-2200PF_M4,2200PF,63V; code: 01010048
J7 = DB2公头座子: 连接器_DB2公头,电源接头; code: 0207001
L4 = 100uH贴片功率电感: 贴片功率电感_SLF12575T-101M1R9-PF_100uH±20%,额定电流1.9A,12.5x12.5; code: 01030003
L11 = SLF6025T-100M1R0-PF: SPM3010T-4R7M-LR
Q1 = MMBT2222: NPN三极管_MMBT2222_表贴SOT23; code: 01050001
R4 R85 = 10K贴片电阻: 贴片电阻_10K±5%,0603; code: 01020011
R22 R25 R27 = 10Ω贴片电阻
R23 = 10Ω贴片电阻: 贴片电阻_10Ω±5%,0603; code: 01020104
R78 R79 R89 R90 R97 R98 R110 R111 = 0.004Ω检流电阻-大封装: 贴片电阻_LR12DTDSR004_0.004±5%,2W,2512; code: 01020105
R80 = 6.2K贴片电阻: 贴片电阻_6.2K±5%,0603; code: 01020106
R82 = 2K贴片电阻: 贴片电阻_2K±5%,0603; code: 01020086
R83 = 12.4K贴片电阻: code: 01020125
R84 R88 R93 R94 R100 R101 R123 = 1K贴片电阻: 贴片电阻_1K±5%,0603; code: 01020082
R86 = 1.5K贴片电阻: 贴片电阻_1.5K±5%,0603; code: 01020063
R87 = 0Ω贴片电阻: 贴片电阻_0Ω±5%,0603; code: 01020010
U4 U11 = LM1117S-3.3: LDO_LM1117S-3.3_1A输出,SOT223; code: 01060031
U9 = LM2576HVDP-ADJ: 稳压集成电路_LM2576HVDP-ADJ_3A输出,SOIC8; code: 03020005; Maker: HTC
U10 = TPS63700DRCR: 负压转换器_TPS63700DRCR_360mA输出,VSON-10; Maker: TI
U12 = IRF7240TR: P-MOSFET_IRF7240TR_SOIC8; Maker: IR; code: 01050003
U14 U15 U18 U19 = MAX4080TASA: 电流检测放大器_MAX4080TASA_SOIC8; Maker: MAXIM; code: 01060003

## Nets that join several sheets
3.3VCC: 1-MCU (22 pins), 4-POWER (C60.2 C76.2 C78.2 U11.2)
3.3VCC1: 1-MCU (10 pins), 2-RJ45 (9 pins), 4-POWER (C13.2 C17.2 C19.2 U4.2)
3.3VCC11: 1-MCU (J1.1 L2.1), 2-RJ45 (J4.10 J4.12)
+5V: 3-RF (13 pins), 4-POWER (16 pins)
GND: 1-MCU (35 pins), 2-RJ45 (37 pins), 3-RF (27 pins), 4-POWER (89 pins)
I_SENSOR1: 1-MCU (U2.23), 4-POWER (C92.2 C93.2 R93.2)
I_SENSOR2: 1-MCU (U2.24), 4-POWER (C103.2 C104.2 R100.2)
I_SENSOR3: 1-MCU (U2.15), 4-POWER (C94.2 C95.2 R94.2)
I_SENSOR4: 1-MCU (U2.16), 4-POWER (C105.2 C106.2 R101.2)
LINKLED: 1-MCU (R77.2), 2-RJ45 (R50.2 U5.25)
PTT_SW: 1-MCU (U2.4), 4-POWER (R88.1)
SPI2_MISO: 1-MCU (R17.2), 2-RJ45 (U5.34)
SPI2_MOSI: 1-MCU (R16.2), 2-RJ45 (U5.35)
SPI2_NSS: 1-MCU (R19.2), 2-RJ45 (R41.1 U5.32)
SPI2_SCK: 1-MCU (R18.2), 2-RJ45 (U5.33)
Start_soft: 1-MCU (U2.2), 4-POWER (R4.1 U10.4)
V+: 1-MCU (U2.9), 3-RF (C53.2 C54.2 R62.2)
V-: 1-MCU (U2.10), 3-RF (C62.2 C63.2 R70.2)
VOLT_DEC: 1-MCU (U2.22), 4-POWER (R84.1)
W5500_INTn: 1-MCU (U2.37), 2-RJ45 (U5.36)
W5500_RSTn: 1-MCU (U2.38), 2-RJ45 (R39.1 U5.37)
